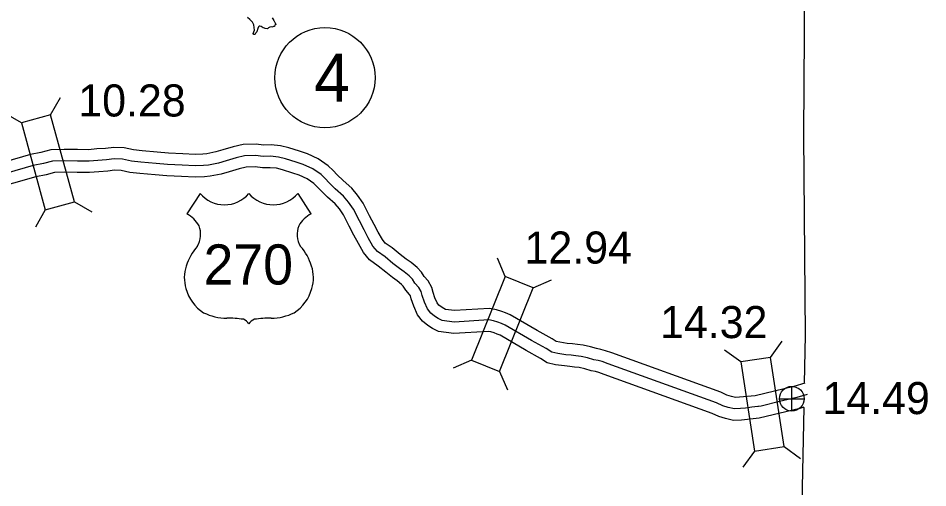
# Model space of a CAD drawing. Extents: x -83719 to 153526, y -11835 to 11446.
# Drawn here: x -3582.6 to -3183.5, y -3452.8 to -3246.8 of the extents above; entities that cross this region are included whole.
import ezdxf

# ---------------------------------------------------------------- set-up
doc = ezdxf.new("R2010")
doc.units = 0
for name, color, linetype in [('Level 15', 7, 'Continuous'), ('Level 2', 7, 'Continuous'), ('Level 20', 7, 'Continuous'), ('Level 22', 7, 'Continuous'), ('Level 25', 7, 'Continuous'), ('Level 26', 7, 'Continuous'), ('Level 27', 7, 'Continuous'), ('Level 58', 7, 'Continuous'), ('Level 59', 7, 'Continuous'), ('Level 9', 7, 'Continuous')]:
    doc.layers.add(name, color=color, linetype=linetype)

msp = doc.modelspace()

# ---------------------------------------------------------------- linework, layer by layer
at = {"layer": 'Level 15'}
for points in [[(-3259.21, -3412.38), (-3266.06, -3413.08), (-3267.84, -3413.17), (-3269.71, -3412.71), (-3271.72, -3412.11), (-3274.38, -3410.91), (-3322.14, -3393.63), (-3324.97, -3392.66), (-3327.03, -3392.1), (-3328.87, -3391.73), (-3331.56, -3390.95), (-3334.71, -3390.24), (-3337.25, -3389.9), (-3339.46, -3389.62), (-3341.7, -3389.42), (-3344.92, -3388.95), (-3346.54, -3388.56), (-3348.36, -3387.42), (-3354.86, -3383.83), (-3366.81, -3376.88), (-3368.81, -3376.08), (-3370.47, -3375.45), (-3372.79, -3374.66), (-3375.87, -3374.12), (-3391.19, -3375.06), (-3395.14, -3374.54), (-3395.91, -3374.15), (-3397.02, -3373.46), (-3398.02, -3372.63), (-3398.76, -3371.7), (-3399.75, -3369.48), (-3400.59, -3367.04), (-3401.15, -3364.88), (-3402.67, -3362.05), (-3404.55, -3360.05), (-3405.67, -3358.18), (-3407.62, -3356.19), (-3410.24, -3354.01), (-3412.43, -3352.49), (-3415.1, -3350.42), (-3418.55, -3347.57), (-3421.54, -3345.42), (-3422.82, -3343.87), (-3424.63, -3340.71), (-3426.46, -3337.32), (-3428.49, -3333.43), (-3431.23, -3327.98), (-3433.7, -3324.4), (-3436.29, -3321.3), (-3440.09, -3317.91), (-3442.62, -3315.51), (-3444.4, -3313.59), (-3446.57, -3311.47), (-3450.94, -3308.51), (-3455.76, -3306.26), (-3459.21, -3305.16), (-3463.93, -3303.71), (-3467.55, -3302.76), (-3471.68, -3302.33), (-3474.93, -3302.44), (-3478.17, -3302.02), (-3483.98, -3302.14), (-3488.29, -3303.22), (-3492.84, -3304.55), (-3495.96, -3305.46), (-3499.84, -3306.23), (-3501.65, -3306.39), (-3504.97, -3306.56), (-3510.41, -3306.28), (-3516.71, -3305.91), (-3521.7, -3305.48), (-3528.3, -3304.94), (-3532.08, -3304.53), (-3536.15, -3303.69), (-3540.72, -3303.42), (-3544.32, -3303.88), (-3548.08, -3304.15), (-3551.75, -3304.46), (-3556.57, -3304.43), (-3562.52, -3304.3), (-3568.28, -3304.5), (-3572.67, -3305.69), (-3577.19, -3306.6), (-3596.91, -3312.2)], [(-3257.53, -3422.26), (-3265.29, -3423.06), (-3268.79, -3423.24), (-3272.34, -3422.37), (-3275.24, -3421.5), (-3278.15, -3420.17), (-3325.44, -3403.06), (-3327.91, -3402.23), (-3329.34, -3401.84), (-3331.25, -3401.45), (-3334.06, -3400.64), (-3336.47, -3400.09), (-3338.54, -3399.82), (-3340.55, -3399.56), (-3342.86, -3399.35), (-3346.8, -3398.78), (-3350.47, -3397.91), (-3353.44, -3396.04), (-3359.79, -3392.52), (-3371.2, -3385.89), (-3372.43, -3385.4), (-3373.85, -3384.86), (-3375.29, -3384.37), (-3376.43, -3384.17), (-3391.54, -3385.1), (-3398.17, -3384.23), (-3400.83, -3382.87), (-3402.89, -3381.59), (-3405.19, -3379.67), (-3407.37, -3376.95), (-3409.07, -3373.14), (-3410.17, -3369.92), (-3410.53, -3368.55), (-3410.86, -3367.93), (-3412.57, -3366.11), (-3413.64, -3364.33), (-3414.4, -3363.55), (-3416.3, -3361.98), (-3418.35, -3360.55), (-3421.36, -3358.22), (-3424.66, -3355.49), (-3428.42, -3352.79), (-3431.07, -3349.58), (-3433.37, -3345.58), (-3435.3, -3342), (-3437.39, -3337.99), (-3439.86, -3333.09), (-3441.68, -3330.45), (-3443.5, -3328.27), (-3446.86, -3325.27), (-3449.75, -3322.53), (-3451.56, -3320.56), (-3452.91, -3319.25), (-3455.89, -3317.23), (-3459.41, -3315.59), (-3462.19, -3314.7), (-3466.66, -3313.33), (-3469.34, -3312.63), (-3472.03, -3312.35), (-3475.4, -3312.46), (-3478.71, -3312.04), (-3482.65, -3312.12), (-3485.67, -3312.88), (-3490.03, -3314.14), (-3493.57, -3315.19), (-3498.42, -3316.14), (-3500.95, -3316.37), (-3504.97, -3316.57), (-3510.96, -3316.27), (-3517.43, -3315.88), (-3522.54, -3315.44), (-3529.25, -3314.9), (-3533.63, -3314.42), (-3537.46, -3313.63), (-3540.38, -3313.46), (-3543.32, -3313.83), (-3547.3, -3314.12), (-3551.37, -3314.46), (-3556.7, -3314.43), (-3562.45, -3314.31), (-3566.77, -3314.45), (-3570.37, -3315.43), (-3574.84, -3316.32), (-3594.65, -3321.95)], [(-3237.49, -3406.94), (-3242.24, -3408.33), (-3259.21, -3412.38)], [(-3237.92, -3417.48), (-3239.68, -3418), (-3257.53, -3422.26)]]:
    msp.add_lwpolyline(points, dxfattribs=at)
at = {"layer": 'Level 2'}
for points in [[(-3237.56, -3406.9), (-3237.14, -3386.02), (-3237.87, -3298.09), (-3237.31, -3208.94), (-3237.73, -3121.6), (-3237.4, -3033.39), (-3238.1, -2956.03), (-3239.03, -2867.93), (-3239.61, -2799.15)], [(-3239.06, -3557.79), (-3238.91, -3473.58), (-3237.78, -3417.63)]]:
    msp.add_lwpolyline(points, dxfattribs=at)
at = {"layer": 'Level 20'}
for p, q in [((-3568.43, -3289.2), (-3564.06, -3281.56)), ((-3581.16, -3292.67), (-3588.8, -3288.31)), ((-3558, -3327.4), (-3550.36, -3331.76)), ((-3570.74, -3330.87), (-3575.1, -3338.52)), ((-3368.92, -3360.08), (-3372.38, -3351.99)), ((-3356.67, -3365), (-3348.58, -3361.54)), ((-3252.53, -3395.56), (-3247.34, -3388.46)), ((-3265.57, -3397.58), (-3272.68, -3392.39)), ((-3383.66, -3396.84), (-3391.75, -3400.3)), ((-3371.41, -3401.75), (-3367.95, -3409.84)), ((-3246.46, -3434.69), (-3239.35, -3439.89)), ((-3259.5, -3436.72), (-3264.7, -3443.82))]:
    msp.add_line(p, q, dxfattribs=at)
for points in [[(-3581.16, -3292.67), (-3570.74, -3330.87), (-3558, -3327.4), (-3568.43, -3289.2)], [(-3368.92, -3360.08), (-3383.66, -3396.84), (-3371.41, -3401.75), (-3356.67, -3365)], [(-3246.46, -3434.69), (-3252.53, -3395.56), (-3265.57, -3397.58), (-3259.5, -3436.72)]]:
    msp.add_lwpolyline(points, close=True, dxfattribs=at)
at = {"layer": 'Level 22'}
for p, q in [((-3502.85, -3323.64), (-3508.62, -3332.56)), ((-3459.95, -3323.64), (-3454.19, -3332.56))]:
    msp.add_line(p, q, dxfattribs=at)
for centre, radius, start, end in [((-3492.11, -3314.6), 14.04, 220.075, 319.6701), ((-3470.7, -3314.6), 14.04, 220.3299, 319.925), ((-3516.16, -3345.51), 14.99, 30.7809, 59.9883), ((-3446.65, -3345.51), 14.99, 120.0117, 149.2191), ((-3512.86, -3341.56), 10.28, 328.8105, 21.2108), ((-3449.95, -3341.56), 10.28, 158.7892, 211.1895), ((-3485.99, -3362.62), 23.97, 138.9565, 162.6913), ((-3476.82, -3362.62), 23.97, 17.3087, 41.0435), ((-3493.9, -3360.66), 15.84, 160.9576, 197.3819), ((-3468.9, -3360.66), 15.84, 342.6181, 19.0424), ((-3491.33, -3360.61), 18.33, 195.1074, 237.1312), ((-3471.48, -3360.61), 18.33, 302.8688, 344.8926), ((-3490.98, -3354.84), 23.53, 244.0771, 269.5779), ((-3471.82, -3354.84), 23.53, 270.4221, 295.9229), ((-3490.44, -3421.48), 43.11, 81.1942, 90.9539), ((-3485.05, -3382.83), 4.13, 28.0342, 72.9864), ((-3477.76, -3382.83), 4.13, 107.0136, 151.9658), ((-3472.37, -3421.48), 43.11, 89.0461, 98.8058)]:
    msp.add_arc(centre, radius, start, end, dxfattribs=at)
at = {"layer": 'Level 26'}
for p, q in [((-3243.19, -3419.14), (-3243.19, -3408.3)), ((-3248.61, -3413.72), (-3237.77, -3413.72))]:
    msp.add_line(p, q, dxfattribs=at)
msp.add_circle((-3243.19, -3413.72), 5.42, dxfattribs=at)
at = {"layer": 'Level 27'}
msp.add_circle((-3448.03, -3272.87), 22, dxfattribs=at)
at = {"layer": 'Level 59'}
for points in [[(-3256.67, -3416.99), (-3257.74, -3417.09), (-3258.04, -3417.13), (-3260.68, -3417.4), (-3263.44, -3417.84), (-3265.68, -3418.07), (-3268.31, -3418.21), (-3271.03, -3417.54), (-3273.48, -3416.81), (-3276.27, -3415.54), (-3323.79, -3398.34), (-3326.44, -3397.44), (-3328.18, -3396.97), (-3330.06, -3396.59), (-3332.81, -3395.79), (-3335.59, -3395.16), (-3337.9, -3394.86), (-3340.01, -3394.59), (-3342.28, -3394.39), (-3345.86, -3393.87), (-3348.51, -3393.23), (-3350.9, -3391.73), (-3357.33, -3388.18), (-3369.01, -3381.38), (-3370.62, -3380.74), (-3372.16, -3380.16), (-3374.04, -3379.51), (-3376.15, -3379.14), (-3391.37, -3380.08), (-3396.65, -3379.39), (-3398.37, -3378.51), (-3399.95, -3377.53), (-3401.61, -3376.15), (-3403.07, -3374.33), (-3404.41, -3371.31), (-3405.38, -3368.48), (-3405.84, -3366.72), (-3406.77, -3364.99), (-3408.56, -3363.08), (-3409.65, -3361.26), (-3411.01, -3359.87), (-3413.27, -3358), (-3415.39, -3356.52), (-3418.23, -3354.32), (-3421.61, -3351.53), (-3424.98, -3349.1), (-3426.95, -3346.72), (-3429, -3343.14), (-3430.88, -3339.66), (-3432.94, -3335.71), (-3435.54, -3330.54), (-3437.69, -3327.43), (-3439.9, -3324.78), (-3443.48, -3321.59), (-3446.18, -3319.02), (-3447.98, -3317.07), (-3449.74, -3315.36), (-3453.41, -3312.87), (-3457.58, -3310.92), (-3460.7, -3309.93), (-3465.3, -3308.52), (-3468.45, -3307.7), (-3471.86, -3307.34), (-3475.16, -3307.45), (-3478.44, -3307.03), (-3483.32, -3307.13), (-3486.98, -3308.05), (-3491.44, -3309.34), (-3494.76, -3310.33), (-3499.13, -3311.19), (-3501.3, -3311.38), (-3504.97, -3311.57), (-3510.68, -3311.28), (-3517.07, -3310.9), (-3522.12, -3310.46), (-3528.77, -3309.92), (-3532.85, -3309.47), (-3536.81, -3308.66), (-3540.55, -3308.44), (-3543.82, -3308.85), (-3547.69, -3309.14), (-3551.56, -3309.46), (-3556.64, -3309.43), (-3562.48, -3309.31), (-3567.52, -3309.47), (-3571.52, -3310.56), (-3576.02, -3311.46), (-3595.78, -3317.07)], [(-3236.46, -3411.85), (-3240.96, -3413.17), (-3248.61, -3414.99), (-3256.67, -3416.99)]]:
    msp.add_lwpolyline(points, dxfattribs=at)
at = {"layer": 'Level 9'}
msp.add_lwpolyline([(-3471.22, -3246.6), (-3470.92, -3246.99), (-3470.41, -3247.76), (-3470.1, -3248.32), (-3470.03, -3248.55), (-3469.89, -3248.75), (-3469.65, -3249.48), (-3470.01, -3249.75), (-3470.04, -3249.86), (-3470.21, -3250.33), (-3470.34, -3250.33), (-3470.57, -3250.43), (-3470.84, -3250.53), (-3471.37, -3250.64), (-3471.7, -3250.61), (-3472.17, -3250.65), (-3472.8, -3250.96), (-3473.3, -3251.44), (-3474.23, -3251.35), (-3474.6, -3251.15), (-3475.14, -3250.99), (-3476.08, -3250.47), (-3476.55, -3250.28), (-3476.69, -3250.31), (-3476.89, -3250.28), (-3477.22, -3250.52), (-3477.54, -3251.23), (-3477.92, -3252.67), (-3478.32, -3253.17), (-3478.64, -3253.71), (-3478.98, -3253.95), (-3479.18, -3253.85), (-3479.48, -3253.52), (-3478.97, -3252.05), (-3479.05, -3250.85), (-3479.23, -3249.68), (-3479.88, -3248.55), (-3480.93, -3247.4), (-3482.01, -3246.44)], dxfattribs=at)

# ---------------------------------------------------------------- texts
at = {"layer": 'Level 22'}
msp.add_text('270', height=17.6, dxfattribs=at).set_placement((-3501.31, -3363.61))
at = {"layer": 'Level 25'}
msp.add_text('14.49', height=14.08, dxfattribs=at).set_placement((-3229.73, -3420.47))
at = {"layer": 'Level 27'}
msp.add_text('4', height=21.12, dxfattribs=at).set_placement((-3452.76, -3283.43))
at = {"layer": 'Level 58'}
for s, p in [('10.28', (-3556.26, -3289.89)), ('12.94', (-3360.45, -3354.43)), ('14.32', (-3300.99, -3387.13))]:
    msp.add_text(s, height=14.08, dxfattribs=at).set_placement(p)

doc.saveas('drawing.dxf')
